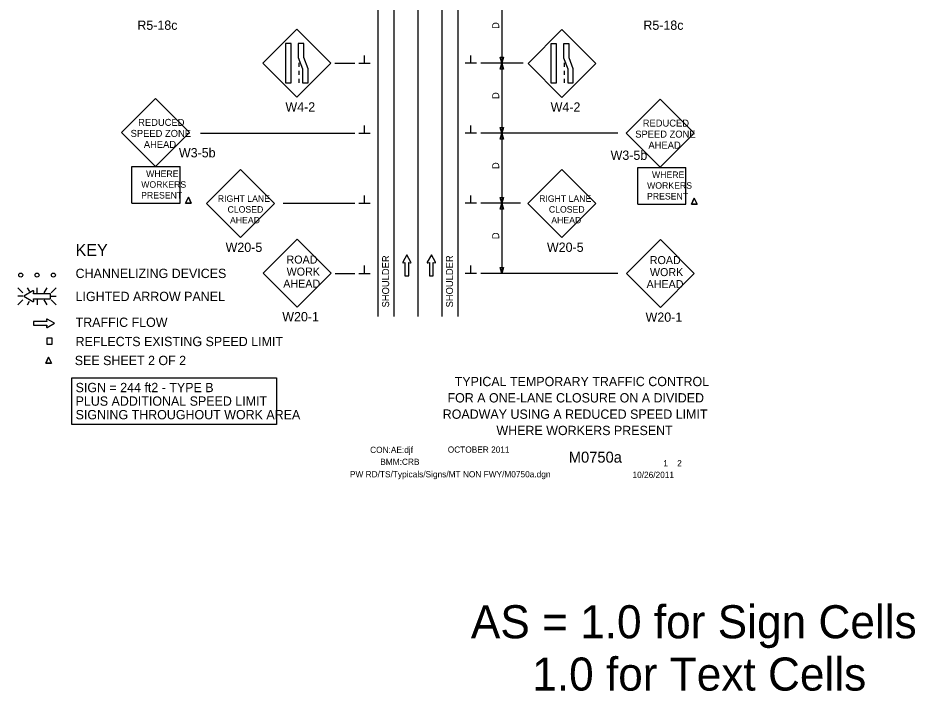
# Model space of a CAD drawing. Extents: x 16739 to 18475, y 5720 to 6924.
# Drawn here: x 16739 to 17635, y 5720 to 6393 of the extents above; entities that cross this region are included whole.
import ezdxf

# ---------------------------------------------------------------- set-up
doc = ezdxf.new("R2010")
doc.units = 0
for name, color, linetype in [('ALI_LEGAL_EX', 7, 'Continuous'), ('BORDER', 7, 'Continuous'), ('BORDER_SIGNAL_WO', 7, 'Continuous'), ('MT_SCRATCH_LEVEL_E', 7, 'Continuous'), ('PAVT_EDGE_EX', 7, 'Continuous'), ('TRAFFIC_SIGNS_PR', 7, 'Continuous'), ('TYPICAL_TEXT_DIMEN_EX', 7, 'Continuous'), ('TYPICAL_TEXT_DIMEN_PR', 7, 'Continuous')]:
    doc.layers.add(name, color=color, linetype=linetype)

msp = doc.modelspace()

# ---------------------------------------------------------------- linework, layer by layer
at = {"layer": 'ALI_LEGAL_EX'}
msp.add_line((17138.25, 6923.7), (17138.25, 6094.51), dxfattribs=at)
for points in [[(17138.25, 6323.7), (17138.25, 6298.7)], [(17138.25, 6223.7), (17138.25, 6198.7)], [(17138.25, 6123.7), (17138.25, 6098.7)]]:
    msp.add_lwpolyline(points, dxfattribs=at)
at = {"layer": 'MT_SCRATCH_LEVEL_E'}
for p, q in [((17127.36, 6155.9), (17123.25, 6148.66)), ((17127.36, 6155.9), (17123.25, 6148.66)), ((17131.51, 6148.66), (17127.36, 6155.9)), ((17131.51, 6148.66), (17127.36, 6155.9)), ((17151.92, 6155.9), (17147.81, 6148.66)), ((17151.92, 6155.9), (17147.81, 6148.66)), ((17156.07, 6148.66), (17151.92, 6155.9)), ((17156.07, 6148.66), (17151.92, 6155.9)), ((17123.73, 6147.98), (17125.51, 6148.29)), ((17123.73, 6147.98), (17125.51, 6148.29)), ((17125.51, 6148.29), (17125.51, 6135.03)), ((17125.51, 6148.29), (17125.51, 6135.03)), ((17129.25, 6135.03), (17129.25, 6148.29)), ((17129.25, 6148.29), (17131.03, 6147.98)), ((17129.25, 6135.03), (17129.25, 6148.29)), ((17129.25, 6148.29), (17131.03, 6147.98)), ((17148.29, 6147.98), (17150.07, 6148.29)), ((17148.29, 6147.98), (17150.07, 6148.29)), ((17150.07, 6148.29), (17150.07, 6135.03)), ((17150.07, 6148.29), (17150.07, 6135.03)), ((17153.81, 6135.03), (17153.81, 6148.29)), ((17153.81, 6148.29), (17155.59, 6147.98)), ((17153.81, 6135.03), (17153.81, 6148.29)), ((17153.81, 6148.29), (17155.59, 6147.98)), ((17125.51, 6135.03), (17129.25, 6135.03)), ((17125.51, 6135.03), (17129.25, 6135.03)), ((17150.07, 6135.03), (17153.81, 6135.03)), ((17150.07, 6135.03), (17153.81, 6135.03)), ((16767.45, 6089.53), (16754.19, 6089.53)), ((16754.19, 6089.53), (16754.19, 6085.79)), ((16767.45, 6089.53), (16754.19, 6089.53)), ((16754.19, 6089.53), (16754.19, 6085.79)), ((16767.14, 6091.31), (16767.45, 6089.53)), ((16767.14, 6091.31), (16767.45, 6089.53)), ((16775.06, 6087.68), (16767.82, 6091.79)), ((16775.06, 6087.68), (16767.82, 6091.79)), ((16754.19, 6085.79), (16767.45, 6085.79)), ((16754.19, 6085.79), (16767.45, 6085.79)), ((16767.45, 6085.79), (16767.14, 6084.02)), ((16767.45, 6085.79), (16767.14, 6084.02)), ((16767.82, 6083.54), (16775.06, 6087.68)), ((16767.82, 6083.54), (16775.06, 6087.68))]:
    msp.add_line(p, q, dxfattribs=at)
for centre, start, end in [((17123.66, 6148.43), 150.42484, 279.96381), ((17123.66, 6148.43), 150.42484, 279.96381), ((17131.1, 6148.44), 260.03619, 29.77312), ((17131.1, 6148.44), 260.03619, 29.77312), ((17148.22, 6148.43), 150.42484, 279.96381), ((17148.22, 6148.43), 150.42484, 279.96381), ((17155.66, 6148.44), 260.03619, 29.77312), ((17155.66, 6148.44), 260.03619, 29.77312), ((16767.6, 6091.39), 60.42484, 189.96381), ((16767.6, 6091.39), 60.42484, 189.96381), ((16767.6, 6083.95), 170.03619, 299.77312), ((16767.6, 6083.95), 170.03619, 299.77312)]:
    msp.add_arc(centre, 0.463, start, end, dxfattribs=at)
at = {"layer": 'PAVT_EDGE_EX'}
for p, q in [((17098.25, 6923.7), (17098.25, 6094.51)), ((17114.25, 6923.7), (17114.25, 6094.51)), ((17162.25, 6923.7), (17162.25, 6094.51)), ((17178.25, 6923.7), (17178.25, 6094.51))]:
    msp.add_line(p, q, dxfattribs=at)
at = {"layer": 'TRAFFIC_SIGNS_PR'}
for p, q in [((17017.33, 6381.26), (16983.38, 6347.32)), ((17051.27, 6347.32), (17017.33, 6381.26)), ((17282.42, 6381.13), (17248.48, 6347.19)), ((17316.36, 6347.19), (17282.42, 6381.13)), ((16983.38, 6347.32), (17017.33, 6313.38)), ((17017.33, 6313.38), (17051.27, 6347.32)), ((17019.38, 6347.94), (17019.38, 6343.94)), ((17019.38, 6339.94), (17019.38, 6335.94)), ((17248.48, 6347.19), (17282.42, 6313.25)), ((17282.42, 6313.25), (17316.36, 6347.19)), ((17284.47, 6347.8), (17284.47, 6343.8)), ((17284.47, 6339.8), (17284.47, 6335.8)), ((17019.38, 6331.94), (17019.38, 6327.94)), ((17284.47, 6331.8), (17284.47, 6327.8)), ((16876.21, 6312.12), (16842.27, 6278.18)), ((16910.16, 6278.18), (16876.21, 6312.12)), ((17380.59, 6311.39), (17346.65, 6277.45)), ((17414.53, 6277.45), (17380.59, 6311.39)), ((16842.27, 6278.18), (16876.21, 6244.24)), ((16876.21, 6244.24), (16910.16, 6278.18)), ((17346.65, 6277.45), (17380.59, 6243.51)), ((17380.59, 6243.51), (17414.53, 6277.45)), ((16852.63, 6244.14), (16900.63, 6244.14)), ((16852.63, 6207.5), (16852.63, 6244.14)), ((16900.63, 6207.5), (16900.63, 6244.14)), ((16961.02, 6241.09), (16927.08, 6207.15)), ((16994.96, 6207.15), (16961.02, 6241.09)), ((17282.19, 6241.11), (17248.25, 6207.17)), ((17316.13, 6207.17), (17282.19, 6241.11)), ((17358.26, 6243.15), (17406.26, 6243.15)), ((17358.26, 6206.51), (17358.26, 6243.15)), ((17406.26, 6206.51), (17406.26, 6243.15)), ((16852.63, 6207.5), (16900.63, 6207.5)), ((16927.08, 6207.15), (16961.02, 6173.2)), ((16961.02, 6173.2), (16994.96, 6207.15)), ((17248.25, 6207.17), (17282.19, 6173.23)), ((17282.19, 6173.23), (17316.13, 6207.17)), ((17358.26, 6206.51), (17406.26, 6206.51)), ((17017.66, 6171.75), (16983.72, 6137.81)), ((17051.6, 6137.81), (17017.66, 6171.75)), ((17380.78, 6171.26), (17346.84, 6137.32)), ((17414.72, 6137.32), (17380.78, 6171.26)), ((16983.72, 6137.81), (17017.66, 6103.87)), ((17017.66, 6103.87), (17051.6, 6137.81)), ((17346.84, 6137.32), (17380.78, 6103.38)), ((17380.78, 6103.38), (17414.72, 6137.32)), ((16738.65, 6123.11), (16743.58, 6118.18)), ((16750.41, 6119.29), (16748.2, 6123.11)), ((16757.73, 6118.18), (16757.73, 6123.11)), ((16764.96, 6118.18), (16767.81, 6123.11)), ((16771.88, 6118.18), (16776.81, 6123.12)), ((16743.58, 6114.62), (16738.65, 6114.62)), ((16738.65, 6106.14), (16743.58, 6111.07)), ((16748.16, 6106.13), (16750.27, 6109.8)), ((16757.73, 6111.07), (16757.73, 6106.13)), ((16767.86, 6106.13), (16765.01, 6111.07)), ((16771.88, 6114.62), (16776.81, 6114.62)), ((16771.88, 6111.07), (16776.81, 6106.13))]:
    msp.add_line(p, q, dxfattribs=at)
for points in [[(17006.21, 6366.99), (17006.21, 6327.94), (17011.82, 6327.94), (17011.82, 6366.99)], [(17018.88, 6366.99), (17018.88, 6353.02), (17023.06, 6341.91), (17023.06, 6327.94), (17028.67, 6327.94), (17028.67, 6341.91), (17024.49, 6353.02), (17024.49, 6366.99)], [(17271.3, 6366.86), (17271.3, 6327.8), (17276.92, 6327.8), (17276.92, 6366.86)], [(17283.97, 6366.86), (17283.97, 6352.88), (17288.15, 6341.78), (17288.15, 6327.8), (17293.77, 6327.8), (17293.77, 6341.78), (17289.59, 6352.88), (17289.59, 6366.86)], [(16767.37, 6066.61), (16772.96, 6066.61), (16772.96, 6072.78), (16767.37, 6072.78)]]:
    msp.add_lwpolyline(points, close=True, dxfattribs=at)
for points in [[(16909.06, 6213.67), (16906.27, 6207.5)], [(16906.27, 6207.5), (16909.06, 6213.67)], [(16906.27, 6207.5), (16911.86, 6207.5)], [(16911.86, 6207.5), (16906.27, 6207.5)], [(16911.86, 6207.5), (16909.06, 6213.67)], [(16909.06, 6213.67), (16911.86, 6207.5)], [(17414.7, 6212.68), (17411.9, 6206.51)], [(17411.9, 6206.51), (17414.7, 6212.68)], [(17411.9, 6206.51), (17417.49, 6206.51)], [(17417.49, 6206.51), (17411.9, 6206.51)], [(17417.49, 6206.51), (17414.7, 6212.68)], [(17414.7, 6212.68), (17417.49, 6206.51)], [(16753.66, 6119.9), (16744.37, 6114.62), (16753.66, 6109.3)], [(16754.53, 6109.93), (16754.13, 6112.2), (16771.14, 6112.2), (16771.14, 6117), (16754.13, 6117), (16754.53, 6119.28)], [(16769.34, 6053.84), (16766.55, 6047.67)], [(16766.55, 6047.67), (16769.34, 6053.84)], [(16772.14, 6047.67), (16769.34, 6053.84)], [(16769.34, 6053.84), (16772.14, 6047.67)], [(16766.55, 6047.67), (16772.14, 6047.67)], [(16772.14, 6047.67), (16766.55, 6047.67)]]:
    msp.add_lwpolyline(points, dxfattribs=at)
for centre in [(16741.44, 6135.74), (16757.74, 6135.74), (16774.04, 6135.74)]:
    msp.add_circle(centre, 2, dxfattribs=at)
for centre, radius, start, end in [((16753.94, 6119.38), 0.598, 350.73078, 118.89165), ((16753.94, 6109.83), 0.597, 241.48329, 9.95933)]:
    msp.add_arc(centre, radius, start, end, dxfattribs=at)
at = {"layer": 'TYPICAL_TEXT_DIMEN_EX'}
msp.add_lwpolyline([(16792.55, 6033.03), (16997.25, 6033.03), (16997.25, 5986.52), (16792.55, 5986.52)], close=True, dxfattribs=at)
at = {"layer": 'TYPICAL_TEXT_DIMEN_PR'}
for p, q in [((17222.25, 6417.44), (17222.25, 6347.44)), ((17085.12, 6347.44), (17085.12, 6355.22)), ((17191.38, 6347.44), (17191.38, 6355.22)), ((17222.25, 6347.44), (17220.68, 6353.3)), ((17220.68, 6353.3), (17222.25, 6353.3)), ((17222.25, 6347.44), (17220.68, 6353.3)), ((17220.68, 6353.3), (17222.25, 6353.3)), ((17222.25, 6353.3), (17223.82, 6353.3)), ((17223.82, 6353.3), (17222.25, 6347.44)), ((17222.25, 6353.3), (17223.82, 6353.3)), ((17223.82, 6353.3), (17222.25, 6347.44)), ((17055.33, 6347.44), (17075.25, 6347.44)), ((17079.5, 6347.44), (17090.75, 6347.44)), ((17197, 6347.44), (17185.75, 6347.44)), ((17243.61, 6347.44), (17201.25, 6347.44)), ((17220.68, 6341.57), (17222.25, 6347.44)), ((17222.25, 6341.57), (17220.68, 6341.57)), ((17222.25, 6347.44), (17222.25, 6277.44)), ((17222.25, 6347.44), (17223.82, 6341.57)), ((17223.82, 6341.57), (17222.25, 6341.57)), ((16921.18, 6277.44), (17075.25, 6277.44)), ((17079.5, 6277.44), (17090.75, 6277.44)), ((17085.12, 6277.44), (17085.12, 6285.22)), ((17197, 6277.44), (17185.75, 6277.44)), ((17191.38, 6277.44), (17191.38, 6285.22)), ((17338.22, 6277.44), (17201.25, 6277.44)), ((17222.25, 6277.44), (17220.68, 6283.3)), ((17220.68, 6283.3), (17222.25, 6283.3)), ((17220.68, 6271.57), (17222.25, 6277.44)), ((17220.68, 6271.57), (17222.25, 6277.44)), ((17222.25, 6283.3), (17223.82, 6283.3)), ((17223.82, 6283.3), (17222.25, 6277.44)), ((17222.25, 6277.44), (17222.25, 6207.44)), ((17222.25, 6277.44), (17223.82, 6271.57)), ((17222.25, 6277.44), (17223.82, 6271.57)), ((17222.25, 6271.57), (17220.68, 6271.57)), ((17222.25, 6271.57), (17220.68, 6271.57)), ((17223.82, 6271.57), (17222.25, 6271.57)), ((17223.82, 6271.57), (17222.25, 6271.57)), ((17085.12, 6207.44), (17085.12, 6215.22)), ((17191.38, 6207.44), (17191.38, 6215.22)), ((17003.74, 6207.44), (17075.25, 6207.44)), ((17079.5, 6207.44), (17090.75, 6207.44)), ((17197, 6207.44), (17185.75, 6207.44)), ((17241.08, 6207.44), (17201.25, 6207.44)), ((17222.25, 6207.44), (17220.68, 6213.3)), ((17220.68, 6213.3), (17222.25, 6213.3)), ((17222.25, 6207.44), (17220.68, 6213.3)), ((17220.68, 6213.3), (17222.25, 6213.3)), ((17220.68, 6201.57), (17222.25, 6207.44)), ((17222.25, 6213.3), (17223.82, 6213.3)), ((17223.82, 6213.3), (17222.25, 6207.44)), ((17222.25, 6213.3), (17223.82, 6213.3)), ((17223.82, 6213.3), (17222.25, 6207.44)), ((17222.25, 6207.44), (17222.25, 6137.44)), ((17222.25, 6207.44), (17223.82, 6201.57)), ((17222.25, 6201.57), (17220.68, 6201.57)), ((17223.82, 6201.57), (17222.25, 6201.57)), ((17085.12, 6137.44), (17085.12, 6145.22)), ((17191.38, 6137.44), (17191.38, 6145.22)), ((17222.25, 6137.44), (17220.68, 6143.3)), ((17220.68, 6143.3), (17222.25, 6143.3)), ((17222.25, 6143.3), (17223.82, 6143.3)), ((17223.82, 6143.3), (17222.25, 6137.44)), ((17055.74, 6137.44), (17075.25, 6137.44)), ((17079.5, 6137.44), (17090.75, 6137.44)), ((17197, 6137.44), (17185.75, 6137.44)), ((17338.22, 6137.44), (17201.25, 6137.44))]:
    msp.add_line(p, q, dxfattribs=at)

# ---------------------------------------------------------------- texts
at = {"layer": 'BORDER'}
for s, p in [('TYPICAL TEMPORARY TRAFFIC CONTROL', (17175.21, 6024.8)), ('FOR A ONE-LANE CLOSURE ON A DIVIDED', (17168.02, 6008.5)), ('ROADWAY USING A REDUCED SPEED LIMIT ', (17163.25, 5992.2)), ('WHERE WORKERS PRESENT', (17216.92, 5975.9))]:
    msp.add_text(s, height=9.3, dxfattribs=at).set_placement(p)
at = {"layer": 'BORDER_SIGNAL_WO'}
for s, height, p in [('CON:AE:djf', 6.2, (17090.69, 5958.06)), ('    OCTOBER 2011    ', 6.2, (17159.08, 5958.34)), ('    M0750a   ', 11, (17272.86, 5948.38)), ('BMM:CRB   ', 6.2, (17100.81, 5946.17)), (' 1    2 ', 6.2, (17381.45, 5944.7)), ('PW RD/TS/Typicals/Signs/MT NON FWY/M0750a.dgn    ', 6.2, (17070.55, 5933.71)), ('10/26/2011    ', 6.2, (17352.93, 5933.13)), ('AS = 1.0 for Sign Cells', 33.0301, (17191.35, 5772.93)), ('     1.0 for Text Cells', 33.0301, (17191.35, 5720.7))]:
    msp.add_text(s, height=height, dxfattribs=at).set_placement(p)
at = {"layer": 'TRAFFIC_SIGNS_PR'}
for s, height, p in [('R5-18c', 9.3, (16857.99, 6380.76)), ('R5-18c', 9.3, (17363.79, 6380.76)), ('W4-2', 9.3, (17006.02, 6299.08)), ('W4-2', 9.3, (17271.12, 6298.95)), ('REDUCED', 7, (16858.79, 6284.81)), ('REDUCED', 7, (17363.16, 6284.09)), ('SPEED ZONE', 7, (16851.28, 6273.81)), ('SPEED ZONE', 7, (17355.65, 6273.09)), ('AHEAD', 7, (16864.48, 6262.81)), ('AHEAD', 7, (17368.85, 6262.09)), ('W3-5b', 9.3, (16899.55, 6253.33)), ('W3-5b', 9.3, (17331.04, 6250.85)), ('WHERE', 6.5, (16866.77, 6233.75)), ('WHERE', 6.5, (17372.4, 6232.76)), ('WORKERS', 6.5, (16861.86, 6223)), ('WORKERS', 6.5, (17367.49, 6222.01)), ('PRESENT', 6.5, (16861.77, 6212.25)), ('RIGHT LANE', 6.5, (16938.42, 6208.89)), ('RIGHT LANE', 6.5, (17259.59, 6208.91)), ('PRESENT', 6.5, (17367.41, 6211.26)), ('CLOSED', 6.5, (16948.16, 6198.14)), ('CLOSED', 6.5, (17269.33, 6198.16)), ('AHEAD', 6.5, (16950.59, 6187.39)), ('AHEAD', 6.5, (17271.76, 6187.41)), ('W20-5', 9.3, (16946.24, 6158.9)), ('W20-5', 9.3, (17267.41, 6158.93)), ('ROAD', 8, (17007.09, 6147.23)), ('ROAD', 8, (17370.21, 6146.73)), ('WORK', 8, (17007.22, 6135.23)), ('WORK', 8, (17370.35, 6134.73)), ('AHEAD', 8, (17003.86, 6123.23)), ('AHEAD', 8, (17366.98, 6122.73)), ('W20-1', 9.3, (17002.87, 6089.57)), ('W20-1', 9.3, (17366, 6089.08))]:
    msp.add_text(s, height=height, dxfattribs=at).set_placement(p)
at = {"layer": 'TYPICAL_TEXT_DIMEN_EX'}
for s, height, p in [('KEY', 12, (16796.28, 6154.84)), ('CHANNELIZING DEVICES', 9.3, (16796.28, 6132.79)), ('LIGHTED ARROW PANEL', 9.3, (16796.28, 6109.8)), ('TRAFFIC FLOW', 9.3, (16796.28, 6084)), ('REFLECTS EXISTING SPEED LIMIT', 9.3, (16796.26, 6064.77)), ('SEE SHEET 2 OF 2', 9.3, (16795.44, 6045.83)), ('SIGN = 244 ft2 - TYPE B', 9.3, (16796.28, 6018.79)), ('PLUS ADDITIONAL SPEED LIMIT', 9.3, (16796.28, 6005.24)), ('SIGNING THROUGHOUT WORK AREA', 9.3, (16796.28, 5991.69))]:
    msp.add_text(s, height=height, dxfattribs=at).set_placement(p)
at = {"layer": 'TYPICAL_TEXT_DIMEN_PR'}
for s, p in [('D', (17219.69, 6381.66)), ('D', (17219.69, 6311.66)), ('D', (17219.69, 6241.66)), ('D', (17219.69, 6171.66)), ('SHOULDER', (17109.67, 6103.45)), ('SHOULDER', (17173.53, 6103.45))]:
    msp.add_text(s, height=7, rotation=90, dxfattribs=at).set_placement(p)

doc.saveas('drawing.dxf')
